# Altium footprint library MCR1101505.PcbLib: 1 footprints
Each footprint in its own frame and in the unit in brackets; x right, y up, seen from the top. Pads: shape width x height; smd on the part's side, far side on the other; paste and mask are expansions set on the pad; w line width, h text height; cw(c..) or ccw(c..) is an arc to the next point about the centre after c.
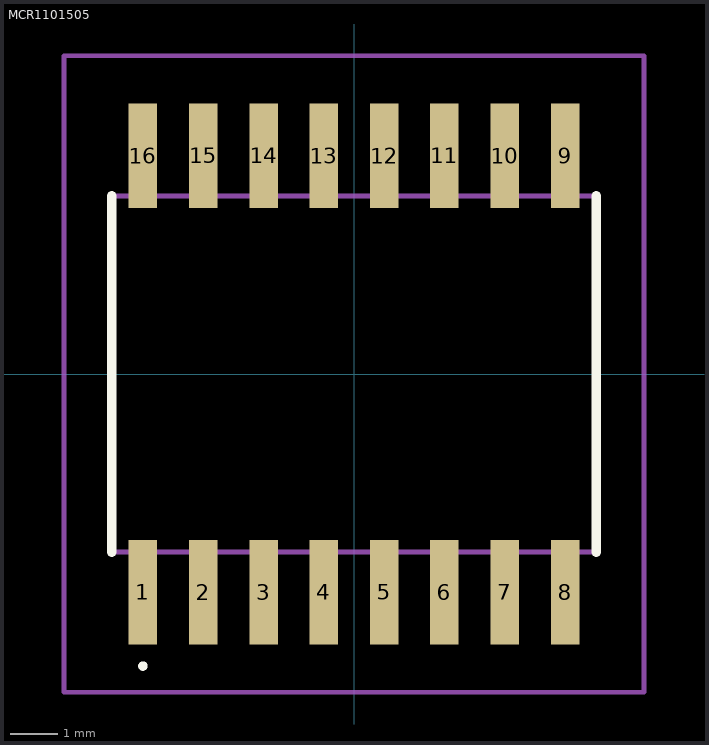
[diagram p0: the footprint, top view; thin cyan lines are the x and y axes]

## MCR1101505 [mm]
pads (16):
  rect 0.6x2.2 smd: 1(-4.445,-4.6) 2(-3.175,-4.6) 3(-1.905,-4.6) 4(-0.635,-4.6) 5(0.635,-4.6) 6(1.905,-4.6) 7(3.175,-4.6) 8(4.445,-4.6) 9(4.445,4.6) 10(3.175,4.6) 11(1.905,4.6) 12(0.635,4.6) 13(-0.635,4.6) 14(-1.905,4.6) 15(-3.175,4.6) 16(-4.445,4.6)
Top Overlay:
  lines w0.1: -4.445,-6.2 -4.445,-6.2 ; -4.445,-6.2 ccw(c-4.445,-6.15) -4.445,-6.1 ; -4.445,-6.2 cw(c-4.445,-6.15) -4.445,-6.1 ; -4.445,-6.1 -4.445,-6.1
  lines w0.2: -5.105,-3.75 -5.105,3.75 ; 5.105,-3.75 5.105,3.75
Mechanical 15:
  lines w0.1: -5.105,-3.75 5.105,-3.75 5.105,3.75 -5.105,3.75 -5.105,-3.75
Mechanical 20:
  lines w0.1: -6.105,-6.7 6.105,-6.7 6.105,6.7 -6.105,6.7 -6.105,-6.7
